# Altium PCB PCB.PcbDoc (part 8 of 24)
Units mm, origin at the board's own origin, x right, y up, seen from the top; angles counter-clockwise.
Board outline 100 x 160 mm, 10 copper layers (TOP_L1, L2, L3, L4, L5, L6, L7, L8, L9, BOTTOM_L10), stack 1.946 mm thick; 1358 components, 1149 nets, 6777 pads, 10914 vias.
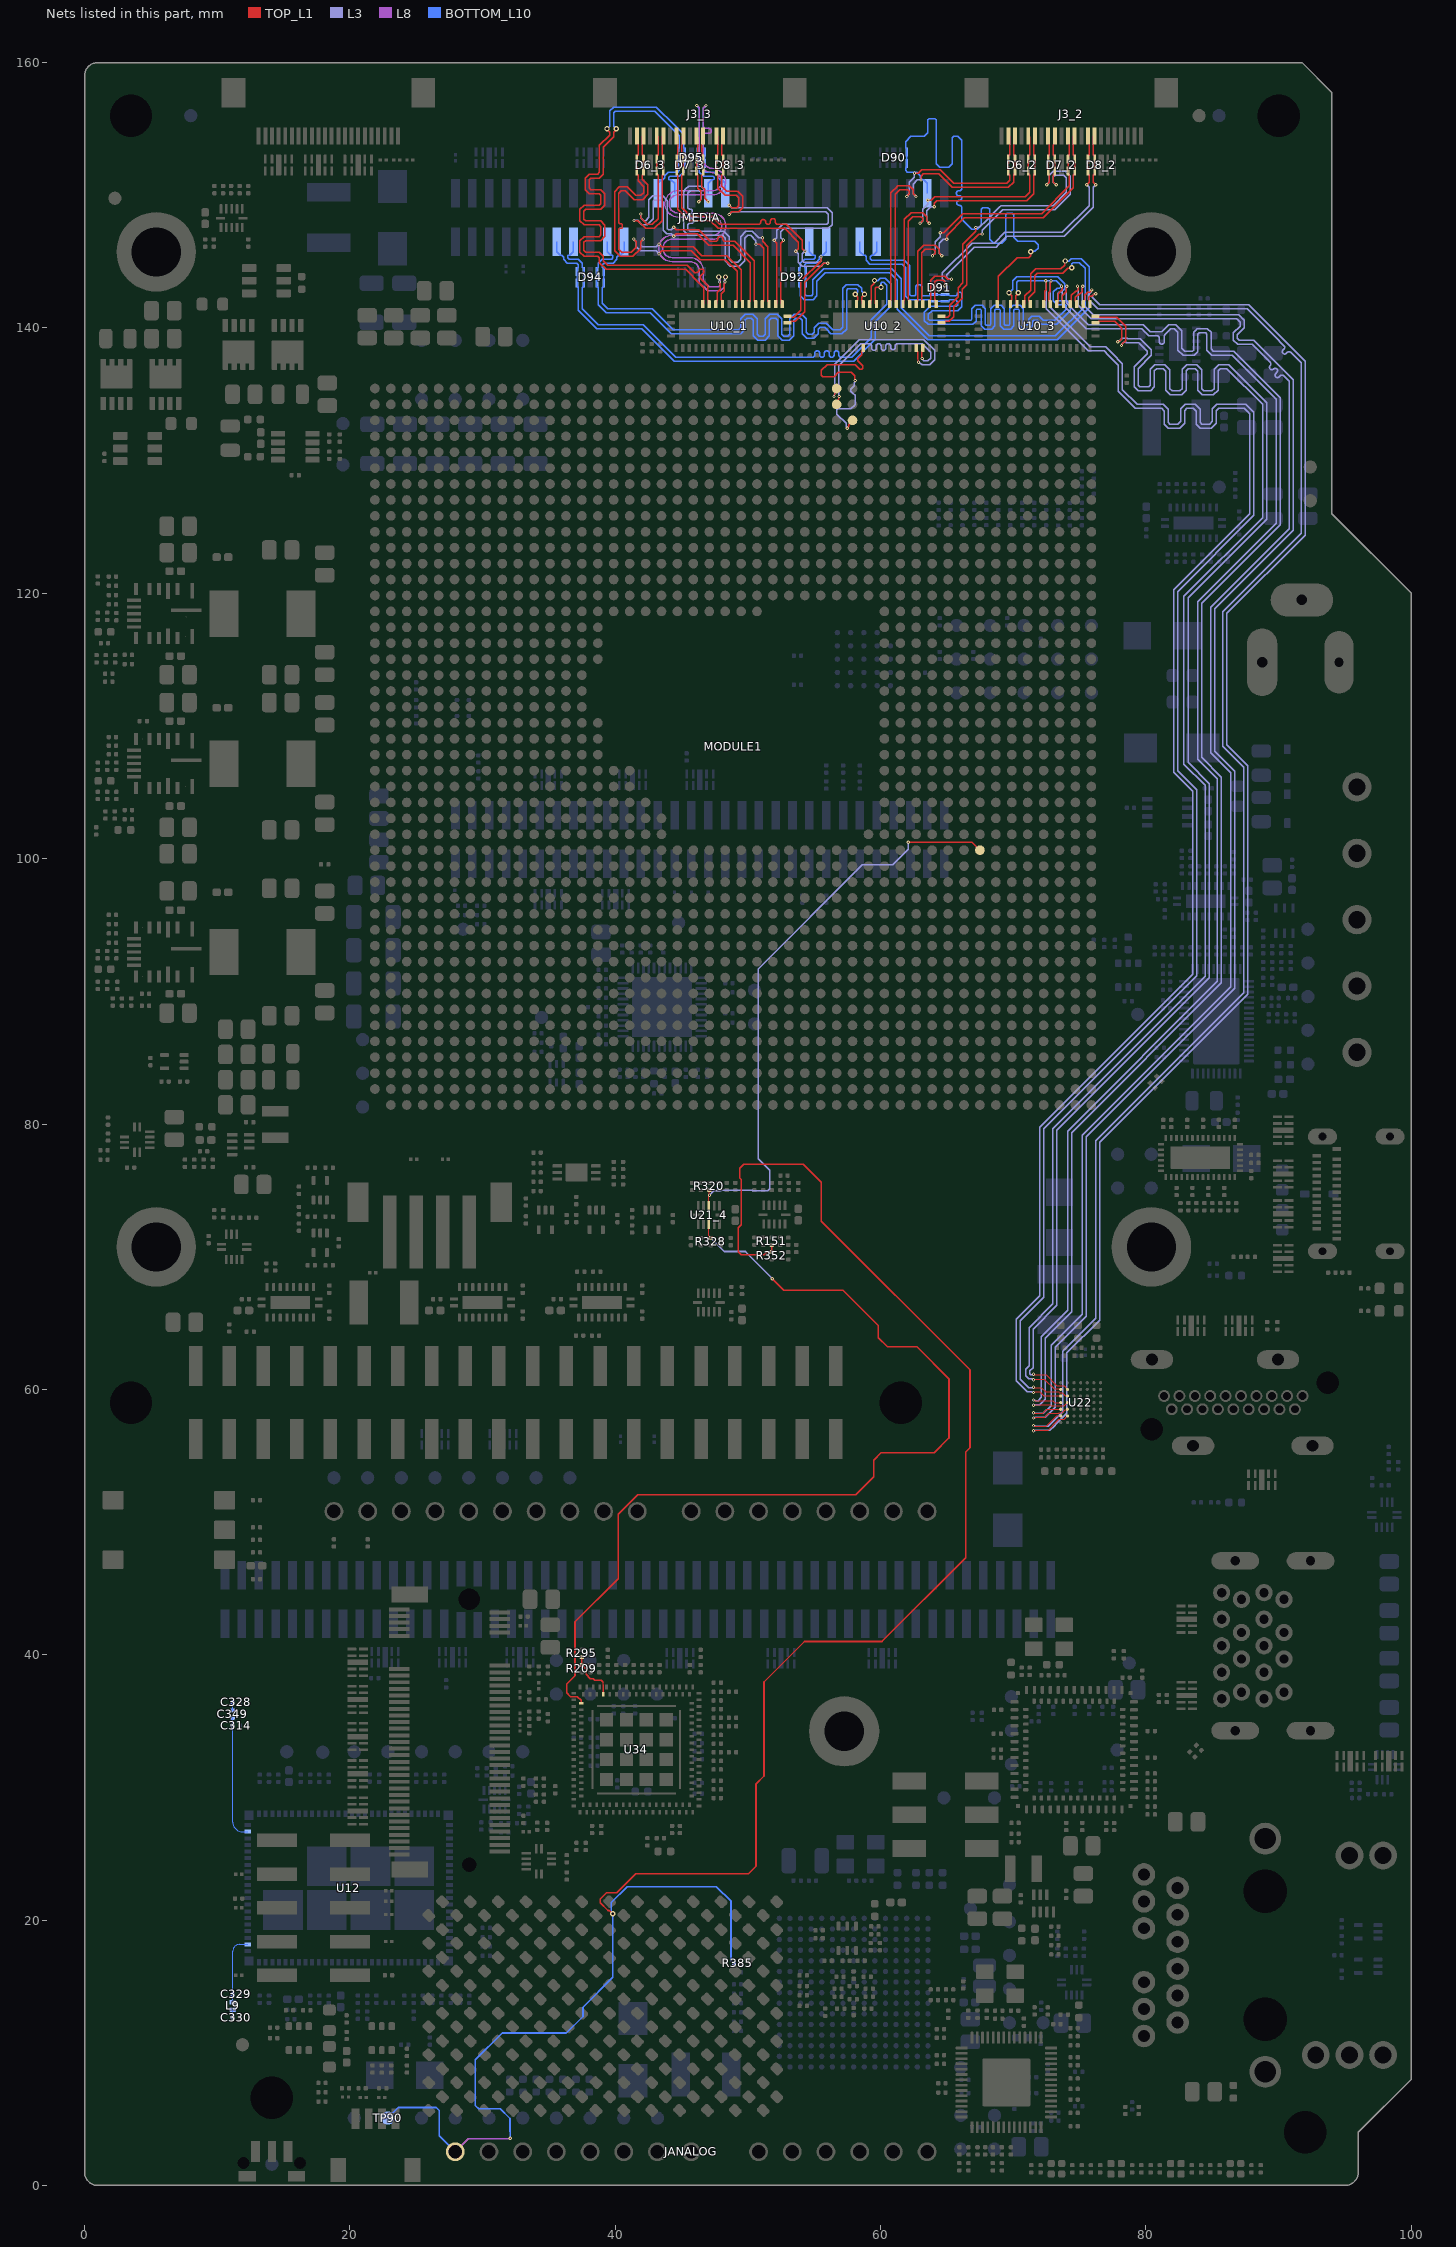
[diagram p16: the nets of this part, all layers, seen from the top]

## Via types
v1: diameter 0.25, hole 0.1, TOP_L1 to L2, tented both sides, 3439 vias
v2: diameter 0.25, hole 0.1, L2 to L3, tented both sides, 2256 vias
v3: diameter 0.25, hole 0.1, L9 to BOTTOM_L10, tented both sides, 1685 vias
v4: diameter 0.25, hole 0.1, L8 to L9, tented both sides, 1675 vias
v5: diameter 0.4, hole 0.2, L3 to L8, tented both sides, 1251 vias
v6: diameter 0.6, hole 0.3, TOP_L1 to BOTTOM_L10, tented both sides, 600 vias
v7: diameter 0.24, hole 0.1, TOP_L1 to L2, tented both sides, 8 vias

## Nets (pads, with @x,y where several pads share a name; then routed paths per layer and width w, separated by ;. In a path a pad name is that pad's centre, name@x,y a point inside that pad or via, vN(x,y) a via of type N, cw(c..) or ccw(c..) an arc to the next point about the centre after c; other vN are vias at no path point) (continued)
A_LN1_3_P: D90.5 D90.6 JMEDIA.4 U10_3.36 | length 43.5
  TOP_L1 w0.109: U10_3.36@68.782,141.791 68.853,141.861 68.853,142.105 68.88,142.132 68.88,143.887 70.297,145.304 71.158,145.304 71.309,145.456 v4(71.309,145.735)
  BOTTOM_L10 w0.109: JMEDIA.4@63.519,150.141 63.519,150.891 63.249,151.161 63.132,151.161 62.985,151.308 62.985,151.468 62.71,151.742 62.017,151.742 61.881,151.878 61.881,152.044 61.979,152.142 D90.6@61.979,152.379 D90.5@61.979,153.254 61.979,153.492 61.882,153.589 61.882,154.04 62.282,154.44 62.348,154.44 63.284,154.44 63.555,154.711 63.555,155.68 63.648,155.773 64.08,155.773 64.173,155.68 64.173,152.391 64.444,152.12 65.128,152.12 65.399,152.391 65.399,154.348 65.492,154.44 65.636,154.44 65.798,154.44 66.104,154.133 66.104,150.934 66.104,150.516 cw(c65.923,150.516) 65.923,150.335 65.886,150.335 ccw(c65.886,150.153) 65.886,149.971 65.923,149.971 cw(c65.923,149.79) 65.923,149.608 65.919,149.608 ccw(c65.919,149.427) 65.919,149.245 65.923,149.245 cw(c65.923,149.063) 66.104,149.063 66.104,148.431 66.104,148.182 66.715,147.571 66.858,147.427 67.285,147.427 67.587,147.729 67.587,148.952 67.711,149.075 68.081,149.075 68.205,148.952 68.205,146.696 68.507,146.394 69.13,146.394 69.432,146.696 69.432,148.529 69.555,148.652 69.925,148.652 70.049,148.529 70.049,146.837 70.351,146.535 71.577,146.535 71.609,146.535 71.876,146.268 71.876,146.012 71.63,145.766 71.44,145.766 71.436,145.762 71.336,145.762 v4(71.309,145.735)
  other v1: 71.309,145.735
  other v2: 71.309,145.735
  other v3: 71.309,145.735
  other v5: 71.309,145.735
A_LN2_1_N: D95.5 D95.6 JMEDIA.36 U10_1.33 | length 40.9
  TOP_L1 w0.109: v3(40.077,155.014) 40.077,154.938 39.879,154.741 39.879,154.407 39.701,154.228 39.109,153.637 39.109,152.975 39.109,151.599 38.8,151.289 38.154,151.289 38.024,151.159 38.024,150.549 38.154,150.418 38.907,150.418 39.216,150.109 39.216,149.246 38.907,148.937 37.769,148.937 37.639,148.807 37.639,148.197 37.769,148.066 38.907,148.066 39.216,147.757 39.216,146.894 38.907,146.585 37.769,146.585 37.639,146.455 37.639,145.845 37.769,145.714 38.8,145.714 39.109,145.405 39.109,145.135 39.109,145.052 39.447,144.713 45.337,144.713 45.437,144.713 45.942,144.209 ccw(c46.071,144.337) 46.199,144.209 46.377,144.386 cw(c46.505,144.258) 46.634,144.386 cw(c46.505,144.258) 46.634,144.13 46.456,143.952 ccw(c46.584,143.823) 46.456,143.695 46.751,143.399 46.985,143.166 46.985,142.132 47.012,142.105 47.012,141.861 U10_1.33@47.082,141.791
  BOTTOM_L10 w0.109: v3(40.077,155.014) 39.879,155.212 39.879,155.909 39.879,156.226 39.994,156.34 42.979,156.34 44.837,154.483 44.837,153.589 44.739,153.492 D95.6@44.739,153.254 44.739,152.142 44.837,152.044 44.837,151.878 44.701,151.742 44.008,151.742 43.733,151.468 43.733,151.308 43.586,151.161 43.47,151.161 43.199,150.891 JMEDIA.36@43.199,150.141
  other v1: 40.077,155.014
  other v2: 40.077,155.014
  other v4: 40.077,155.014
  other v5: 40.077,155.014
A_LN2_1_P: D95.4 D95.7 JMEDIA.34 U10_1.34 | length 41
  TOP_L1 w0.109: v3(39.377,155.014) 39.377,154.938 39.574,154.741 39.574,154.533 38.804,153.763 38.804,152.975 38.804,151.725 38.674,151.594 38.028,151.594 37.719,151.285 37.719,150.423 38.028,150.113 38.781,150.113 38.912,149.983 38.912,149.373 38.781,149.242 37.643,149.242 37.334,148.933 37.334,148.07 37.643,147.761 38.781,147.761 38.912,147.631 38.912,147.021 38.781,146.89 37.643,146.89 37.334,146.581 37.334,145.718 37.643,145.409 38.674,145.409 38.804,145.279 38.804,145.135 38.804,144.925 39.321,144.409 45.311,144.409 46.379,143.341 46.68,143.04 46.68,142.132 46.653,142.105 46.653,141.861 U10_1.34@46.582,141.791
  BOTTOM_L10 w0.109: v3(39.377,155.014) 39.574,155.212 39.574,155.783 39.574,156.352 39.867,156.645 43.106,156.645 44.49,155.261 44.595,155.156 45.142,154.609 45.142,153.589 45.239,153.492 D95.7@45.239,153.254 45.239,152.142 45.141,152.044 45.141,151.752 44.827,151.437 44.134,151.437 44.038,151.341 44.038,151.206 44.082,151.161 44.199,151.161 44.469,150.891 JMEDIA.34@44.469,150.141
  other v1: 39.377,155.014
  other v2: 39.377,155.014
  other v4: 39.377,155.014
  other v5: 39.377,155.014
A_LN2_2_N: D94.1 D94.10 JMEDIA.39 U10_2.33 | length 39.1
  TOP_L1 w0.109: U10_2.33@58.682,141.791 58.612,141.861 58.612,142.105 58.585,142.132 58.585,142.299 58.782,142.496 v3(58.782,142.54)
  BOTTOM_L10 w0.109: D94.1@39.119,143.379 D94.10@39.119,144.254 39.119,144.491 39.021,144.589 39.021,144.755 39.157,144.891 39.85,144.891 40.125,145.165 40.125,145.324 40.272,145.472 40.389,145.472 40.659,145.742 JMEDIA.39@40.659,146.492 ; D94.1@39.119,143.379 39.119,143.142 39.021,143.044 39.021,141.858 39.439,141.441 42.77,141.441 44.355,139.856 49.17,139.856 49.314,139.856 49.469,140.01 49.469,140.688 49.802,141.021 50.363,141.021 50.695,140.688 50.695,139.532 50.85,139.377 51.158,139.377 51.313,139.532 51.313,140.688 51.646,141.021 52.207,141.021 52.54,140.688 52.54,139.532 52.694,139.377 53.002,139.377 53.157,139.532 53.157,140.688 53.49,141.021 54.051,141.021 54.384,140.688 54.384,139.692 54.538,139.537 54.846,139.537 55.001,139.692 55.001,140.01 55.334,140.343 55.895,140.343 56.228,140.01 56.382,139.856 56.599,139.856 56.948,139.856 57.131,140.038 57.131,142.976 57.405,143.25 58.286,143.25 58.561,142.976 58.561,142.762 v3(58.782,142.54)
  other v1: 58.782,142.54
  other v2: 58.782,142.54
  other v4: 58.782,142.54
  other v5: 58.782,142.54
A_LN2_2_P: D94.2 D94.9 JMEDIA.41 U10_2.34 | length 39
  TOP_L1 w0.109: v2(58.082,142.54) 58.082,142.496 58.28,142.299 58.28,142.132 58.253,142.105 58.253,141.861 U10_2.34@58.182,141.791
  BOTTOM_L10 w0.109: D94.2@38.619,143.379 38.619,144.491 38.717,144.589 38.717,144.881 39.031,145.196 39.724,145.196 39.82,145.292 39.82,145.427 39.776,145.472 39.659,145.472 39.389,145.742 JMEDIA.41@39.389,146.492 ; D94.2@38.619,143.379 38.619,143.142 38.717,143.044 38.717,141.732 38.924,141.525 39.313,141.136 42.644,141.136 44.039,139.741 44.229,139.551 49.17,139.551 49.441,139.551 49.773,139.884 49.773,140.562 49.928,140.716 50.236,140.716 50.391,140.562 50.391,139.405 50.724,139.072 51.285,139.072 51.617,139.405 51.617,140.562 51.772,140.716 52.08,140.716 52.235,140.562 52.235,139.405 52.568,139.072 53.129,139.072 53.462,139.405 53.462,140.562 53.616,140.716 53.924,140.716 54.079,140.562 54.079,139.565 54.412,139.233 54.973,139.233 55.306,139.565 55.306,139.884 55.46,140.038 55.768,140.038 55.923,139.884 56.256,139.551 56.599,139.551 57.074,139.551 57.436,139.912 57.436,142.85 57.532,142.946 58.16,142.946 58.256,142.85 58.256,142.714 v2(58.082,142.54)
  other v1: 58.082,142.54
  other v3: 58.082,142.54
  other v4: 58.082,142.54
  other v5: 58.082,142.54
A_LN2_3_N: D91.4 D91.7 JMEDIA.9 U10_3.33 | length 43.7
  TOP_L1 w0.109: U10_3.33@70.282,141.791 70.212,141.861 70.212,142.105 70.171,142.146 70.171,142.42 70.369,142.618 v3(70.369,142.661)
  BOTTOM_L10 w0.109: JMEDIA.9@59.709,146.492 59.709,145.742 59.439,145.472 59.322,145.472 59.227,145.376 59.227,145.211 59.322,145.115 61.761,145.115 62.204,144.671 62.204,142.514 62.3,142.418 62.564,142.418 62.66,142.514 62.66,143.152 62.756,143.248 62.97,143.248 63.083,143.134 63.083,142.514 63.179,142.418 63.655,142.418 63.753,142.515 D91.4@64.866,142.515 ; D91.4@64.866,142.515 64.911,142.47 65.148,142.47 65.201,142.418 65.667,142.418 65.763,142.514 65.763,142.539 65.775,142.551 65.775,142.604 65.878,142.707 66.014,142.707 66.11,142.611 66.11,141.592 65.83,141.313 63.877,141.313 63.604,141.04 63.604,140.669 63.7,140.573 66.674,140.573 66.818,140.573 66.882,140.637 66.882,141.464 67.122,141.704 67.661,141.704 67.901,141.464 67.901,140.275 67.962,140.213 68.249,140.213 68.31,140.275 68.31,141.464 68.55,141.704 69.089,141.704 69.329,141.464 69.329,140.275 69.39,140.213 69.677,140.213 69.738,140.275 69.738,141.464 69.978,141.704 70.517,141.704 70.757,141.464 70.757,140.317 70.818,140.255 71.105,140.255 71.166,140.317 71.166,140.637 71.406,140.877 71.945,140.877 72.185,140.637 72.249,140.573 72.603,140.573 73.137,140.573 73.989,141.425 73.989,141.523 73.989,141.667 73.896,141.76 73.297,141.76 73.026,142.031 73.026,142.716 73.297,142.987 73.464,142.987 73.557,143.079 73.557,143.21 73.227,143.54 71.394,143.54 70.959,143.54 70.37,143.54 70.274,143.445 70.274,142.794 70.369,142.699 v3(70.369,142.661)
  other v1: 70.369,142.661
  other v2: 70.369,142.661
  other v4: 70.369,142.661
  other v5: 70.369,142.661
A_LN2_3_P: D91.5 D91.6 JMEDIA.11 U10_3.34 | length 43.6
  TOP_L1 w0.109: v3(69.669,142.661) 69.669,142.618 69.866,142.42 69.866,142.119 69.853,142.105 69.853,141.861 U10_3.34@69.782,141.791
  BOTTOM_L10 w0.109: JMEDIA.11@58.439,146.492 58.439,145.742 58.71,145.472 58.826,145.472 58.922,145.376 58.922,145.084 59.196,144.81 61.634,144.81 61.899,144.545 61.899,142.387 62.174,142.113 63.655,142.113 63.753,142.015 D91.6@63.865,142.015 ; D91.6@63.991,142.015 D91.5@64.866,142.015 65.103,142.015 65.201,142.113 65.646,142.113 65.805,141.954 65.805,141.718 65.704,141.618 63.751,141.618 63.299,141.166 63.299,140.543 63.574,140.268 66.674,140.268 66.944,140.268 67.187,140.511 67.187,141.338 67.248,141.399 67.535,141.399 67.596,141.338 67.596,140.148 67.836,139.909 68.375,139.909 68.615,140.148 68.615,141.338 68.676,141.399 68.963,141.399 69.024,141.338 69.024,140.148 69.264,139.909 69.803,139.909 70.043,140.148 70.043,141.338 70.104,141.399 70.391,141.399 70.452,141.338 70.452,140.19 70.692,139.95 71.231,139.95 71.471,140.19 71.471,140.511 71.532,140.572 71.819,140.572 71.88,140.511 72.123,140.268 72.603,140.268 73.263,140.268 74.294,141.299 74.294,141.523 74.294,141.793 74.023,142.065 73.423,142.065 73.331,142.157 73.331,142.589 73.423,142.682 73.591,142.682 73.862,142.953 73.862,143.336 73.558,143.64 73.353,143.845 71.085,143.845 ; v3(69.669,142.661) 69.7,142.661 69.969,142.931 69.969,143.571 70.244,143.845 71.085,143.845
  other v1: 69.669,142.661
  other v2: 69.669,142.661
  other v4: 69.669,142.661
  other v5: 69.669,142.661
A_LN3_1_N: D95.2 D95.9 JMEDIA.30 U10_1.31 | length 41
  TOP_L1 w0.109: U10_1.31@48.082,141.791 48.012,141.861 48.012,142.105 47.985,142.132 47.985,142.566 48.214,142.796 48.214,143.323 48.243,143.351 48.243,143.451 v2(48.27,143.478)
  L3 w0.104: v2(48.27,143.478) 48.287,143.495 48.287,143.823 v5(48.304,143.84)
  L8 w0.104: v3(46.139,156.765) 46.327,156.577 46.327,153.796 46.327,152.706 ccw(c47.319,152.706) 47.319,151.714 cw(c47.319,151.027) 47.319,150.34 44.735,150.34 ccw(c44.735,149.348) 44.735,148.356 47.328,148.356 cw(c47.328,147.669) 47.328,146.982 44.275,146.982 ccw(c44.275,145.99) 44.275,144.998 45.64,144.998 cw(c45.64,144.311) 46.327,144.311 46.327,144.107 46.327,143.416 46.951,142.793 47.915,142.793 48.207,143.084 48.207,143.601 48.248,143.642 48.248,143.784 v5(48.304,143.84)
  BOTTOM_L10 w0.109: v3(46.139,156.765) 46.337,156.567 46.337,153.589 46.239,153.492 D95.9@46.239,153.254 46.239,152.142 46.337,152.044 46.337,151.752 46.651,151.437 47.344,151.437 47.44,151.341 47.44,151.206 47.396,151.161 47.279,151.161 47.009,150.891 JMEDIA.30@47.009,150.141
  other v1: 48.27,143.478
  other v4: 46.139,156.765
A_LN3_1_P: D95.1 D95.10 JMEDIA.28 U10_1.32 | length 40.9
  TOP_L1 w0.109: U10_1.32@47.582,141.791 47.653,141.861 47.653,142.105 47.68,142.132 47.68,142.693 47.91,142.923 47.91,143.307 47.881,143.336 47.881,143.435 v2(47.854,143.462)
  L3 w0.104: v5(47.804,143.84) 47.829,143.815 47.829,143.487 v2(47.854,143.462)
  L8 w0.104: v3(46.839,156.765) 46.836,156.765 46.632,156.56 46.632,156.051 46.632,155.213 ccw(c46.811,155.213) 46.811,155.034 47.057,155.034 cw(c47.057,154.855) 47.057,154.676 46.811,154.676 ccw(c46.811,154.497) 46.632,154.497 46.632,154.087 46.632,153.796 46.632,152.706 ccw(c47.319,152.706) 47.319,152.019 cw(c47.319,151.027) 47.319,150.035 44.735,150.035 ccw(c44.735,149.348) 44.735,148.661 47.328,148.661 cw(c47.328,147.669) 47.328,146.677 44.275,146.677 ccw(c44.275,145.99) 44.275,145.303 45.64,145.303 cw(c45.64,144.311) 46.632,144.311 46.632,144.107 46.632,143.542 47.077,143.097 47.789,143.097 47.902,143.21 47.902,143.601 47.861,143.642 47.861,143.784 v5(47.804,143.84)
  BOTTOM_L10 w0.109: v3(46.839,156.765) 46.642,156.567 46.642,153.589 46.739,153.492 D95.10@46.739,153.254 D95.1@46.739,152.379 46.739,152.142 46.641,152.044 46.641,151.878 46.777,151.742 47.47,151.742 47.745,151.468 47.745,151.308 47.892,151.161 48.009,151.161 48.279,150.891 JMEDIA.28@48.279,150.141
  other v1: 47.854,143.462
  other v4: 46.839,156.765
A_LN3_2_N: D94.4 D94.7 JMEDIA.45 U10_2.31 | length 39.1
  TOP_L1 w0.109: U10_2.31@59.682,141.791 59.612,141.861 59.612,142.105 59.585,142.132 59.585,142.981 59.68,143.077 v3(60.028,143.077)
  BOTTOM_L10 w0.109: JMEDIA.45@36.849,146.492 36.849,145.742 36.579,145.472 36.462,145.472 36.418,145.427 36.418,145.292 36.514,145.196 37.207,145.196 37.521,144.881 37.521,144.589 37.619,144.491 D94.4@37.619,143.379 ; D94.4@37.619,143.379 37.619,143.142 37.521,143.044 37.521,141.441 38.721,140.241 42.124,140.241 43.703,138.662 44.575,137.789 53.558,137.789 54.854,137.789 ccw(c54.854,137.971) 55.036,137.971 55.036,138.091 cw(c55.217,138.091) 55.399,138.091 55.399,137.971 ccw(c55.58,137.971) 55.762,137.971 55.762,138.091 cw(c55.944,138.091) 56.125,138.091 56.125,137.971 ccw(c56.307,137.971) 56.488,137.971 56.488,138.091 cw(c56.67,138.091) 56.852,138.091 56.852,137.971 ccw(c57.033,137.971) 57.033,137.789 57.451,137.789 57.83,137.789 59.304,139.264 59.304,140.611 59.483,140.789 60.462,141.768 60.462,143.206 60.238,143.43 60.102,143.43 60.006,143.334 60.006,143.099 v3(60.028,143.077)
  other v1: 60.028,143.077
  other v2: 60.028,143.077
  other v4: 60.028,143.077
  other v5: 60.028,143.077
A_LN3_2_P: D94.5 D94.6 JMEDIA.47 U10_2.32 | length 39.2
  TOP_L1 w0.109: U10_2.32@59.182,141.791 59.253,141.861 59.253,142.105 59.28,142.132 59.28,143.133 59.508,143.362 59.508,143.546 v2(59.533,143.572)
  BOTTOM_L10 w0.109: JMEDIA.47@35.579,146.492 35.579,145.742 35.85,145.472 35.966,145.472 36.113,145.324 36.113,145.165 36.388,144.891 37.081,144.891 37.217,144.755 37.217,144.589 37.119,144.491 D94.5@37.119,143.379 ; D94.5@37.119,143.379 37.119,143.142 37.217,143.044 37.217,141.314 38.595,139.936 41.998,139.936 43.592,138.342 44.449,137.485 57.956,137.485 59.609,139.138 59.609,140.485 60.766,141.642 60.766,143.332 60.364,143.735 59.976,143.735 59.791,143.55 59.555,143.55 v2(59.533,143.572)
  other v1: 59.533,143.572
  other v3: 59.533,143.572
  other v4: 59.533,143.572
  other v5: 59.533,143.572
A_LN3_3_N: D92.1 D92.10 JMEDIA.15 U10_3.31 | length 41.9
  TOP_L1 w0.109: U10_3.31@71.282,141.791 71.282,141.966 71.171,142.077 71.171,142.286 71.609,142.724 71.609,143.945 71.804,144.14 73.715,144.14 74.089,144.514 74.368,144.514 v1(74.399,144.545)
  BOTTOM_L10 w0.109: JMEDIA.15@55.899,146.492 55.899,145.742 55.629,145.472 55.512,145.472 55.365,145.324 55.365,145.165 55.09,144.891 54.397,144.891 54.261,144.755 54.261,144.589 54.359,144.491 D92.10@54.359,144.254 D92.1@54.359,143.379 54.359,143.141 54.262,143.044 54.262,142.563 54.382,142.443 54.8,142.443 54.896,142.539 54.896,143.628 55.074,143.806 55.717,144.449 60.826,144.449 61.551,143.724 61.551,141.539 63.674,139.416 73.169,139.416 75.404,141.65 75.404,144.497 74.977,144.924 74.499,144.924 74.399,144.825 v1(74.399,144.545)
  other v2: 74.399,144.545
  other v3: 74.399,144.545
  other v4: 74.399,144.545
  other v5: 74.399,144.545
A_LN3_3_P: D92.2 D92.9 JMEDIA.17 U10_3.32 | length 43.8
  TOP_L1 w0.109: U10_3.32@70.782,141.791 70.853,141.861 70.853,142.119 70.866,142.132 70.866,142.413 71.304,142.851 71.304,144.071 71.678,144.445 73.588,144.445 73.873,144.73 73.873,145.009 v1(73.904,145.04)
  BOTTOM_L10 w0.109: D92.2@53.859,143.379 53.859,144.491 53.957,144.589 53.957,144.881 54.271,145.196 54.964,145.196 55.06,145.292 55.06,145.427 55.016,145.472 54.899,145.472 54.629,145.742 JMEDIA.17@54.629,146.492 ; D92.2@53.859,143.379 53.859,143.141 53.957,143.044 53.957,142.437 54.255,142.138 54.926,142.138 55.201,142.413 55.201,143.502 55.843,144.144 60.7,144.144 61.247,143.598 61.247,141.413 63.548,139.111 73.296,139.111 75.708,141.524 75.708,144.624 75.103,145.229 74.373,145.229 74.184,145.04 v1(73.904,145.04)
  other v2: 73.904,145.04
  other v3: 73.904,145.04
  other v4: 73.904,145.04
  other v5: 73.904,145.04
ANT0_29: C329.2 L9.1 U12.78 | length 5.5
  BOTTOM_L10 w0.09: L9.1@11.167,13.801 C329.2@11.167,14.401 ; 11.167,14.151 11.167,17.654 cw(c11.674,17.654) 11.674,18.161 U12.78@12.3,18.16
ANT0_PI_29: C330.2 L9.2 | length 0.6
  BOTTOM_L10 w0.09: C330.2@11.167,12.651 L9.2@11.167,13.251
ANT1_29: C314.2 C349.2 U12.95 | length 9.4
  BOTTOM_L10 w0.09: C349.2@11.167,35.251 C314.2@11.167,34.651 11.167,27.374 ccw(c11.881,27.374) 11.881,26.66 U12.95@12.3,26.66
ANT1_PI_29: C328.2 C349.1 | length 0.6
  BOTTOM_L10 w0.09: C349.1@11.167,35.801 C328.2@11.167,36.401
B_CLK_1_N: D7_3.1 D7_3.10 J3_3.8 U10_1.20 | length 26
  TOP_L1 w0.109: J3_3.8@44.624,154.475 44.72,154.38 44.72,153.818 44.722,153.816 44.722,153.052 44.624,152.954 D7_3.10@44.624,152.717 D7_3.1@44.624,151.842 44.624,151.604 44.722,151.506 44.722,148.947 45.172,148.497 45.574,148.095 47.165,148.095 47.751,147.509 52.76,147.509 53.795,146.474 53.795,145.986 v2(53.598,145.788) ; U10_1.20@52.982,140.391 53.157,140.391 53.255,140.488 53.572,140.488 54.295,141.211 54.295,143.434 55.724,144.864 v1(56.004,144.865)
  L3 w0.104: v2@53.598,145.78 53.606,145.78 53.8,145.586 53.8,145.138 53.8,144.938 54.089,144.649 55.509,144.649 55.725,144.865 v1(56.004,144.865)
  other v1: 53.598,145.788
  other v2: 56.004,144.865
B_CLK_1_P: D7_3.2 D7_3.9 J3_3.9 U10_1.21 | length 26
  TOP_L1 w0.109: J3_3.9@45.124,154.475 45.029,154.38 45.029,153.818 45.027,153.816 45.027,153.052 45.124,152.954 D7_3.9@45.124,152.717 D7_3.2@45.124,151.842 45.124,151.604 45.027,151.506 45.027,149.073 45.3,148.8 45.7,148.4 47.291,148.4 47.47,148.221 47.878,147.813 49.902,147.813 50.788,147.813 ccw(c50.788,147.995) 50.97,147.995 cw(c51.151,147.995) 51.333,147.995 ccw(c51.515,147.995) 51.696,147.995 51.696,148.06 cw(c51.878,148.06) 52.059,148.06 52.059,147.995 ccw(c52.241,147.995) 52.241,147.813 52.659,147.813 52.887,147.813 54.1,146.6 54.1,145.986 v2(54.298,145.788) ; U10_1.21@52.982,140.891 53.157,140.891 53.255,140.793 53.446,140.793 53.99,141.337 53.99,143.561 55.509,145.08 v1(55.509,145.36)
  L3 w0.104: v2(54.298,145.788) 54.104,145.594 54.104,145.065 54.215,144.954 55.383,144.954 55.509,145.08 v1(55.509,145.36)
  other v1: 54.298,145.788
  other v2: 55.509,145.36
B_CLK_2_N: D7_2.1 D7_2.10 J3_2.8 U10_2.20 | length 24.3
  TOP_L1 w0.109: U10_2.20@64.582,140.391 64.757,140.391 64.855,140.489 65.172,140.489 65.513,140.829 65.513,141.593 66.142,142.223 66.142,142.909 66.5,143.266 66.5,146.194 67.384,147.078 v2(67.664,147.078) ; v1(72.524,150.8) 72.722,150.998 72.722,151.506 72.624,151.604 D7_2.1@72.624,151.842 D7_2.10@72.624,152.717 72.624,152.954 72.722,153.052 72.722,153.816 72.72,153.818 72.72,154.38 J3_2.8@72.624,154.475
  L3 w0.104: v2(67.664,147.078) 67.664,147.358 69.206,148.9 73.12,148.9 73.66,149.44 74.305,150.085 74.305,151.433 73.926,151.811 73.023,151.811 72.722,151.511 72.722,150.998 v1(72.524,150.8)
  other v1: 67.664,147.078
  other v2: 72.524,150.8
B_CLK_2_P: D7_2.2 D7_2.9 J3_2.9 U10_2.21 | length 22.8
  TOP_L1 w0.109: U10_2.21@64.582,140.891 64.757,140.891 64.855,140.793 65.046,140.793 65.208,140.955 65.208,141.719 65.838,142.349 65.838,143.035 66.195,143.393 66.195,146.32 67.169,147.293 v1@67.169,147.573 ; J3_2.9@73.124,154.475 73.029,154.38 73.029,153.818 73.027,153.816 73.027,153.052 73.124,152.954 D7_2.9@73.124,152.717 D7_2.2@73.124,151.842 73.124,151.604 73.027,151.506 73.027,150.998 v1(73.224,150.8)
  L3 w0.104: v1(67.169,147.573) 67.449,147.573 67.997,148.121 68.991,149.116 69.08,149.205 69.702,149.205 72.799,149.205 72.993,149.205 74,150.211 74,151.306 73.8,151.506 73.149,151.506 73.027,151.384 73.027,150.998 v1(73.224,150.8)
  other v2: 67.169,147.573 73.224,150.8
B_CLK_3_N: U10_3.20 U22.F2 | length 113.8
  TOP_L1 w0.064: 73.277,60.282 73.305,60.254 73.821,60.254 U22.F2@74.075,60
  TOP_L1 w0.086: v2(71.517,61.132) 71.548,61.1 71.633,61.1 71.65,61.084 72.475,61.084 73.277,60.282
  TOP_L1 w0.109: U10_3.20@76.182,140.391 76.357,140.391 76.455,140.489 77.65,140.489 78.156,139.983 78.156,139.17 78.005,139.019 77.976,139.019 77.914,138.958 v1(77.876,138.958)
  L3 w0.104: v2(71.517,61.132) 71.493,61.108 71.304,61.108 71.243,61.169 71.243,61.402 71.487,61.646 71.487,64.532 73.289,66.334 73.289,79.532 84.763,91.007 84.763,105.655 83.167,107.252 83.167,119.661 89.09,125.584 89.09,134.379 86.228,137.241 85.476,137.241 85.132,136.897 85.132,135.431 84.96,135.259 84.36,135.259 84.202,135.417 84.202,136.867 83.828,137.241 83.076,137.241 82.732,136.897 82.732,135.431 82.56,135.259 81.96,135.259 81.802,135.417 81.802,136.867 81.428,137.241 80.676,137.241 80.332,136.897 80.332,135.675 80.213,135.557 79.544,135.557 79.402,135.698 79.402,136.936 80.412,137.946 80.412,138.357 79.757,139.012 ; v1(77.876,138.958) 77.916,138.958 77.977,139.019 78.005,139.019 78.198,139.212 78.598,139.212 78.619,139.191 79.578,139.191 79.757,139.012
  other v1: 71.517,61.132
  other v2: 77.876,138.958
B_CLK_3_P: U10_3.21 U22.G2 | length 113.7
  TOP_L1 w0.086: v1(71.517,60.732) 71.548,60.763 71.633,60.763 71.65,60.779 72.349,60.779 73.075,60.053 73.522,60.053 U22.G2@73.575,60
  TOP_L1 w0.109: U10_3.21@76.182,140.891 76.357,140.891 76.455,140.793 77.777,140.793 78.461,140.109 78.461,139.044 78.22,138.804 78.22,138.775 78.159,138.713 v1(78.159,138.675)
  L3 w0.104: v1(71.517,60.732) 71.478,60.732 71.406,60.803 71.178,60.803 70.938,61.042 70.938,61.528 71.182,61.772 71.182,64.658 72.984,66.46 72.984,79.659 84.459,91.133 84.459,105.529 82.862,107.125 82.862,119.787 88.785,125.711 88.785,134.253 86.102,136.936 85.602,136.936 85.437,136.771 85.437,135.305 85.086,134.954 84.234,134.954 83.897,135.291 83.897,136.741 83.702,136.936 83.202,136.936 83.037,136.771 83.037,135.305 82.686,134.954 81.834,134.954 81.497,135.291 81.497,136.741 81.302,136.936 80.802,136.936 80.637,136.771 80.637,135.549 80.34,135.252 79.417,135.252 79.097,135.572 79.097,137.062 80.107,138.072 80.107,138.231 79.452,138.886 78.493,138.886 78.472,138.908 78.324,138.908 78.22,138.803 78.22,138.776 78.159,138.715 v1(78.159,138.675)
  other v2: 71.517,60.732 78.159,138.675
B_LN0_1_N: D6_3.1 D6_3.10 J3_3.2 U10_1.28 | length 26
  TOP_L1 w0.109: J3_3.2@41.72,153.944 41.72,153.786 41.722,153.784 41.722,153.052 41.624,152.954 41.624,151.604 41.712,151.517 41.712,151.084 42.139,150.657 42.139,150.184 41.937,149.982 41.542,149.982 40.888,150.636 40.306,150.636 39.946,150.276 39.946,145.819 40.37,145.395 41.326,145.395 41.902,145.971 41.902,146.502 v1(42.1,146.7) ; v1@43.301,146.302 43.498,146.105 45.866,146.105 46.514,145.456 48.416,145.456 49.485,144.388 49.485,142.063 49.582,141.966 U10_1.28@49.582,141.791
  L3 w0.104: v1(42.1,146.7) 41.902,146.502 41.902,146.237 42.034,146.105 43.102,146.105 v1(43.3,146.302)
  other v2: 43.3,146.302 42.1,146.7
B_LN0_1_P: D6_3.2 D6_3.9 J3_3.3 U10_1.29 | length 26
  TOP_L1 w0.109: v2(41.4,146.7) 41.598,146.502 41.598,146.098 41.2,145.7 40.496,145.7 40.251,145.945 40.251,146.973 40.251,147.391 cw(c40.36,147.391) 40.36,147.5 40.426,147.5 ccw(c40.426,147.609) 40.535,147.609 40.535,147.754 ccw(c40.426,147.754) 40.426,147.863 40.36,147.863 cw(c40.36,147.973) 40.251,147.973 40.251,149.485 40.251,150.15 40.432,150.331 40.762,150.331 41.237,149.856 41.416,149.678 42.063,149.678 42.444,150.058 42.444,150.783 42.016,151.21 42.016,151.496 42.124,151.604 D6_3.9@42.124,152.717 42.124,152.954 42.027,153.052 42.027,153.816 42.029,153.818 42.029,154.38 J3_3.3@42.124,154.475 ; v1@43.301,145.602 43.498,145.8 45.74,145.8 46.388,145.152 48.29,145.152 49.18,144.262 49.18,142.063 49.082,141.966 U10_1.29@49.082,141.791
  L3 w0.104: v2(41.4,146.7) 41.598,146.502 41.598,146.111 41.908,145.8 43.102,145.8 v2(43.3,145.602)
  other v1: 43.3,145.602 41.4,146.7
B_LN0_2_N: D6_2.1 D6_2.10 J3_2.2 U10_2.28 | length 23.3
  TOP_L1 w0.109: U10_2.28@61.182,141.791 61.182,141.966 61.085,142.064 61.085,150.074 61.426,150.415 62.038,150.415 62.166,150.288 62.166,150.107 v1(61.968,149.908) ; v2(62.551,151.648) 62.828,151.648 63.095,151.915 64.5,151.915 64.679,151.736 65.515,150.9 69.5,150.9 69.722,151.122 69.722,151.506 69.624,151.604 D6_2.1@69.624,151.842 D6_2.10@69.624,152.717 69.624,152.954 69.722,153.052 69.722,153.661 69.722,153.768 69.72,153.77 69.72,154.38 J3_2.2@69.624,154.475
  L3 w0.104: v1(61.968,149.908) 62.166,150.106 62.166,150.325 62.16,150.331 62.16,150.968 62.551,151.359 v2(62.551,151.648)
  other v1: 62.551,151.648
  other v2: 61.968,149.908
B_LN0_2_P: D6_2.2 D6_2.9 J3_2.3 U10_2.29 | length 24.3
  TOP_L1 w0.109: U10_2.29@60.682,141.791 60.682,141.966 60.78,142.064 60.78,150.2 60.958,150.379 61.121,150.542 61.3,150.72 62.164,150.72 62.47,150.414 62.47,150.107 v2(62.668,149.908) ; v2(63.046,151.153) 63.046,151.435 63.221,151.61 64.374,151.61 65.389,150.595 69.626,150.595 70.027,150.996 70.027,151.506 70.124,151.604 D6_2.2@70.124,151.842 D6_2.9@70.124,152.717 70.124,152.954 70.027,153.052 70.027,153.673 70.027,153.816 70.029,153.818 70.029,154.38 J3_2.3@70.124,154.475
  L3 w0.104: v2(62.668,149.908) 62.47,150.106 62.47,150.451 62.465,150.457 62.465,150.841 62.777,151.153 v2(63.046,151.153)
  other v1: 62.668,149.908 63.046,151.153
B_LN0_3_N: U10_3.28 U22.F3 | length 113.8
  TOP_L1 w0.064: 73.075,59.805 73.423,59.805 73.473,59.754 73.68,59.754 73.905,59.53
  TOP_L1 w0.084: 73.905,59.53 74.045,59.53 U22.F3@74.075,59.5
  TOP_L1 w0.086: v1(71.517,60.166) 71.548,60.135 71.633,60.135 71.65,60.118 72.113,60.118 72.427,59.805 73.075,59.805
  TOP_L1 w0.109: U10_3.28@72.782,141.791 72.782,141.966 72.685,142.064 72.685,142.644 72.789,142.748 72.789,143.415 72.81,143.435 72.81,143.522 v2(72.836,143.549)
  L3 w0.104: v1(71.517,60.166) 71.489,60.138 71.403,60.138 71.383,60.118 71.173,60.118 70.526,60.766 70.526,65.171 72.289,66.934 72.289,79.632 83.813,91.157 83.813,105.205 82.389,106.629 82.389,120.125 88.129,125.865 88.129,133.64 87.533,134.236 85.35,134.236 85.006,133.892 85.006,132.952 84.805,132.751 84.205,132.751 84.076,132.88 84.076,133.862 83.702,134.236 82.95,134.236 82.606,133.892 82.606,132.952 82.405,132.751 81.805,132.751 81.676,132.88 81.676,133.862 81.302,134.236 79.333,134.236 78.22,135.349 78.22,137.319 77.461,138.078 76.969,138.57 75.792,138.57 72.789,141.573 72.789,143.415 72.809,143.435 72.809,143.521 v2(72.836,143.549)
  other v1: 72.836,143.549
  other v2: 71.517,60.166
B_LN0_3_P: U10_3.29 U22.G3 | length 113.7
  TOP_L1 w0.084: 73.075,59.5 U22.G3@73.575,59.5
  TOP_L1 w0.086: v2(71.517,59.766) 71.548,59.797 71.633,59.797 71.65,59.813 71.987,59.813 72.3,59.5 73.075,59.5
  TOP_L1 w0.109: U10_3.29@72.282,141.791 72.282,141.966 72.38,142.064 72.38,142.77 72.484,142.875 72.484,143.415 72.463,143.435 72.463,143.522 v2(72.436,143.549)
  L3 w0.104: v2(71.517,59.766) 71.489,59.794 71.403,59.794 71.383,59.813 71.047,59.813 70.221,60.639 70.221,65.297 71.984,67.06 71.984,79.759 83.509,91.283 83.509,105.078 82.084,106.503 82.084,120.252 87.824,125.992 87.824,133.514 87.407,133.931 85.476,133.931 85.311,133.766 85.311,132.826 84.931,132.446 84.078,132.446 83.771,132.754 83.771,133.736 83.576,133.931 83.076,133.931 82.911,133.766 82.911,132.826 82.531,132.446 81.678,132.446 81.371,132.754 81.371,133.736 81.176,133.931 79.207,133.931 77.915,135.223 77.915,137.193 77.154,137.953 76.843,138.265 75.666,138.265 72.484,141.447 72.484,141.746 72.484,143.415 72.464,143.435 72.464,143.521 v2(72.436,143.549)
  other v1: 71.517,59.766 72.436,143.549
B_LN1_1_N: D6_3.4 D6_3.7 J3_3.5 U10_1.26 | length 26
  TOP_L1 w0.109: v1(41.907,148.587) 41.909,148.585 41.909,148.306 42.415,147.8 42.8,147.8 43.222,148.222 43.222,151.506 43.124,151.604 D6_3.7@43.124,152.717 43.124,152.954 43.222,153.052 43.222,153.816 43.22,153.818 43.22,154.38 J3_3.5@43.124,154.475 ; v1@44.401,147.6 44.598,147.402 46.296,147.402 47.167,146.531 47.502,146.531 47.556,146.531 ccw(c47.556,146.713) 47.738,146.713 47.738,146.733 cw(c47.92,146.733) 48.101,146.733 48.101,146.713 ccw(c48.283,146.713) 48.283,146.531 49.01,146.531 49.121,146.42 50.485,145.056 50.485,142.063 50.582,141.966 U10_1.26@50.582,141.791
  L3 w0.104: v1(41.907,148.587) 41.9,148.58 41.9,148.314 42.131,148.084 42.284,148.084 42.537,148.337 42.537,149.67 42.812,149.944 43.585,149.944 43.93,149.599 43.93,147.494 44.022,147.402 44.202,147.402 v1(44.4,147.6)
  other v2: 44.4,147.6 41.907,148.587
B_LN1_1_P: D6_3.5 D6_3.6 J3_3.6 U10_1.27 | length 26.1
  TOP_L1 w0.109: v1(41.412,148.092) 41.414,148.09 41.693,148.09 42.289,147.495 42.926,147.495 43.527,148.096 43.527,151.506 43.624,151.604 D6_3.5@43.624,151.842 D6_3.6@43.624,152.717 43.624,152.954 43.527,153.052 43.527,153.816 43.529,153.818 43.529,154.38 J3_3.6@43.624,154.475 ; v1@44.401,146.9 44.598,147.098 46.17,147.098 47.041,146.226 48.883,146.226 50.18,144.93 50.18,142.063 50.082,141.966 U10_1.27@50.082,141.791
  L3 w0.104: v1(41.412,148.092) 41.419,148.099 41.685,148.099 42.005,147.779 42.41,147.779 42.842,148.211 42.842,149.543 42.938,149.64 43.458,149.64 43.626,149.472 43.626,147.368 43.896,147.098 44.202,147.098 v1(44.4,146.9)
  other v2: 44.4,146.9 41.412,148.092
B_LN1_2_N: D6_2.4 D6_2.7 J3_2.5 U10_2.26 | length 22.3
  TOP_L1 w0.109: U10_2.26@62.182,141.791 62.112,141.861 62.112,142.105 62.085,142.132 62.085,148.053 62.426,148.395 63.038,148.395 63.166,148.267 63.166,148.086 v2(62.968,147.888) ; v2(63.551,149.628) 63.828,149.628 64.095,149.895 70.895,149.895 71.222,150.222 71.222,151.506 71.124,151.604 D6_2.4@71.124,151.842 D6_2.7@71.124,152.717 71.124,152.954 71.222,153.052 71.222,153.816 71.22,153.818 71.22,154.38 J3_2.5@71.124,154.475
  L3 w0.104: v2(62.968,147.888) 63.166,148.086 63.166,148.304 63.16,148.31 63.16,148.947 63.551,149.338 v2(63.551,149.628)
  other v1: 62.968,147.888 63.551,149.628
B_LN1_2_P: D6_2.5 D6_2.6 J3_2.6 U10_2.27 | length 23.3
  TOP_L1 w0.109: U10_2.27@61.682,141.791 61.753,141.861 61.753,142.105 61.78,142.132 61.78,148.18 62.3,148.7 63.164,148.7 63.47,148.393 63.47,148.086 v1(63.668,147.888) ; v2(64.046,149.133) 64.046,149.415 64.221,149.59 71.021,149.59 71.527,150.096 71.527,151.506 71.624,151.604 D6_2.5@71.624,151.842 D6_2.6@71.624,152.717 71.624,152.954 71.527,153.052 71.527,153.816 71.529,153.818 71.529,154.38 J3_2.6@71.624,154.475
  L3 w0.104: v1(63.668,147.888) 63.47,148.086 63.47,148.431 63.465,148.436 63.465,148.821 63.777,149.133 v2(64.046,149.133)
  other v1: 64.046,149.133
  other v2: 63.668,147.888
B_LN1_3_N: U10_3.26 U22.F4 | length 113.6
  TOP_L1 w0.064: 72.877,58.75 73.825,58.75
  TOP_L1 w0.084: 72.827,58.8 72.877,58.75 ; 73.825,58.75 73.925,58.85 U22.F4@74.075,59
  TOP_L1 w0.086: v2(71.517,58.8) 71.548,58.831 71.633,58.831 71.65,58.848 72.78,58.848 72.827,58.8
  TOP_L1 w0.109: U10_3.26@73.7,142.083 73.692,142.091 73.692,142.437 73.989,142.734 73.989,143.015 74.01,143.035 74.01,143.122 v2(74.036,143.149)
  L3 w0.104: v2(71.517,58.8) 71.545,58.828 71.631,58.828 71.651,58.848 71.988,58.848 72.407,59.267 72.407,63.852 74.389,65.834 74.389,79.343 85.675,90.629 85.675,106.143 84.189,107.629 84.189,119.237 90.112,125.161 90.112,134.757 86.609,138.26 86.587,138.26 85.106,138.26 85.078,138.26 84.902,138.436 84.902,139.667 84.628,139.941 83.876,139.941 83.597,139.662 83.597,138.331 83.502,138.236 82.92,138.236 82.702,138.454 82.702,139.783 82.249,140.236 81.732,140.236 81.204,139.708 80.33,139.708 79.791,140.247 75.638,140.247 73.989,141.897 73.989,143.015 74.009,143.035 74.009,143.121 v2(74.036,143.149)
  other v1: 71.517,58.8 74.036,143.149
B_LN1_3_P: U10_3.27 U22.G4 | length 113.8
  TOP_L1 w0.084: 73.126,59 U22.G4@73.575,59
  TOP_L1 w0.086: v1(71.517,59.2) 71.548,59.169 71.633,59.169 71.65,59.153 72.973,59.153 73.126,59
  TOP_L1 w0.109: U10_3.27@73.282,141.791 73.353,141.861 73.353,142.071 73.388,142.106 73.388,142.564 73.684,142.86 73.684,143.015 73.663,143.035 73.663,143.122 v2(73.636,143.149)
  L3 w0.104: v1(71.517,59.2) 71.545,59.172 71.631,59.172 71.651,59.153 71.861,59.153 72.102,59.394 72.102,63.978 74.084,65.96 74.084,79.469 85.371,90.755 85.371,106.016 83.884,107.503 83.884,119.364 89.808,125.287 89.808,134.631 86.483,137.955 84.952,137.955 84.597,138.31 84.597,139.541 84.502,139.636 84.002,139.636 83.902,139.536 83.902,138.205 83.628,137.931 82.793,137.931 82.397,138.327 82.397,139.657 82.123,139.931 81.858,139.931 81.509,139.582 81.457,139.53 ccw(c81.674,139.314) 81.454,139.527 ccw(c81.673,139.314) 81.368,139.314 81.368,138.955 cw(c81.189,138.955) 81.01,138.955 81.01,139.224 ccw(c80.831,139.224) 80.831,139.403 80.317,139.403 80.204,139.403 79.665,139.942 75.512,139.942 73.684,141.77 73.684,143.015 73.664,143.035 73.664,143.121 v2(73.636,143.149)
  other v1: 73.636,143.149
  other v2: 71.517,59.2
B_LN2_1_N: D7_3.4 D7_3.7 J3_3.11 U10_1.24 | length 26
  TOP_L1 w0.109: J3_3.11@46.124,154.475 46.22,154.38 46.22,153.818 46.222,153.816 46.222,153.052 46.124,152.954 D7_3.7@46.124,152.717 46.124,151.604 46.222,151.506 46.222,150.527 46.427,150.322 46.427,149.666 46.3,149.538 v2(46.3,149.5) ; v1(51.095,146.795) 51.096,146.515 51.485,146.126 51.485,142.063 51.582,141.966 U10_1.24@51.582,141.791
  L3 w0.104: v2(46.3,149.5) 46.3,149.527 46.498,149.724 46.498,150.227 46.366,150.358 45.645,150.358 45.455,150.169 45.455,149.854 45.455,149.139 ccw(c45.634,149.139) 45.633,148.959 45.64,148.959 cw(c45.638,148.78) 45.817,148.779 cw(c45.638,148.78) 45.637,148.601 ccw(c45.635,148.422) 45.456,148.424 ccw(c45.635,148.422) 45.634,148.243 45.733,148.242 cw(c45.731,148.063) 45.911,148.062 cw(c45.731,148.063) 45.73,147.884 45.635,147.885 ccw(c45.634,147.706) 45.455,147.706 45.455,147.463 45.479,147.439 45.532,147.386 45.639,147.279 47.365,147.279 48.186,147.279 48.582,146.884 48.582,145.177 48.798,144.96 49.231,144.96 49.448,145.177 49.448,146.884 49.843,147.279 50.11,147.279 50.331,147.279 50.816,146.795 v1(51.095,146.795)
  other v1: 46.3,149.5
  other v2: 51.095,146.795
B_LN2_1_P: D7_3.5 D7_3.6 J3_3.12 U10_1.25 | length 26
  TOP_L1 w0.109: J3_3.12@46.624,154.475 46.529,154.38 46.529,153.818 46.527,153.816 46.527,153.052 46.624,152.954 D7_3.6@46.624,152.717 D7_3.5@46.624,151.842 46.624,151.604 46.527,151.506 46.527,150.654 46.732,150.448 46.732,149.768 v2(47,149.5) ; v1(50.6,146.3) 50.88,146.299 51.18,146 51.18,142.063 51.082,141.966 U10_1.25@51.082,141.791
  L3 w0.104: v2(47,149.5) 47,149.527 46.802,149.724 46.802,150.353 46.624,150.532 46.493,150.663 45.518,150.663 45.329,150.473 45.15,150.295 45.15,147.337 45.512,146.974 47.365,146.974 48.06,146.974 48.277,146.758 48.277,145.05 48.672,144.655 49.357,144.655 49.753,145.05 49.753,146.758 49.969,146.974 50.11,146.974 50.205,146.974 50.6,146.579 v1(50.6,146.3)
  other v1: 47,149.5
  other v2: 50.6,146.3
B_LN2_2_N: D7_2.4 D7_2.7 J3_2.11 U10_2.24 | length 22.6
  TOP_L1 w0.109: U10_2.24@63.182,141.791 63.182,141.966 63.085,142.064 63.085,145.665 63.364,145.945 63.975,145.945 64.103,145.817 64.103,145.636 v1(63.906,145.437) ; v2(64.489,147.177) 64.766,147.177 66.193,148.605 72.127,148.605 74.222,150.7 74.222,151.506 74.124,151.604 D7_2.4@74.124,151.842 D7_2.7@74.124,152.717 74.124,152.954 74.222,153.052 74.222,153.816 74.22,153.818 74.22,154.38 J3_2.11@74.124,154.475
  L3 w0.104: v1(63.906,145.437) 64.103,145.635 64.103,145.854 64.098,145.86 64.098,146.497 64.489,146.888 v2(64.489,147.177)
  other v1: 64.489,147.177
  other v2: 63.906,145.437
B_LN2_2_P: D7_2.5 D7_2.6 J3_2.12 U10_2.25 | length 23.6
  TOP_L1 w0.109: U10_2.25@62.682,141.791 62.682,141.966 62.78,142.064 62.78,145.792 63.238,146.249 64.102,146.249 64.408,145.943 64.408,145.636 v2(64.606,145.437) ; v2(64.984,146.682) 64.984,146.964 66.32,148.3 72.253,148.3 74.527,150.573 74.527,151.506 74.624,151.604 D7_2.5@74.624,151.842 D7_2.6@74.624,152.717 74.624,152.954 74.527,153.052 74.527,153.816 74.529,153.818 74.529,154.38 J3_2.12@74.624,154.475
  L3 w0.104: v2(64.606,145.437) 64.408,145.635 64.408,145.98 64.402,145.986 64.402,146.37 64.714,146.682 v2(64.984,146.682)
  other v1: 64.606,145.437 64.984,146.682
B_LN2_3_N: U10_3.24 U22.F5 | length 113.8
  TOP_L1 w0.064: 73.076,58.196 73.422,58.196 73.423,58.198 73.425,58.198 73.473,58.246 73.68,58.246 73.905,58.47
  TOP_L1 w0.084: 73.075,58.195 73.076,58.196 ; 73.905,58.47 74.045,58.47 U22.F5@74.075,58.5
  TOP_L1 w0.086: v1(71.517,57.834) 71.548,57.866 71.633,57.866 71.65,57.882 72.35,57.882 72.663,58.195 73.075,58.195
  TOP_L1 w0.109: U10_3.24@74.782,141.791 74.782,141.966 74.685,142.064 74.685,142.319 74.821,142.456 74.911,142.456 75.189,142.734 75.189,143.015 75.21,143.035 75.21,143.122 v1(75.236,143.149)
  L3 w0.104: v1(71.517,57.834) 71.545,57.862 71.631,57.862 71.651,57.882 72.4,57.882 73.163,58.645 73.163,61 73.163,63.19 75.31,65.337 75.489,65.516 75.489,79.028 86.675,90.215 86.675,106.602 85.168,108.109 85.168,118.832 91.091,124.755 91.091,136.109 88.131,139.069 87.026,139.069 86.883,139.212 86.883,139.495 87.403,140.016 87.403,140.566 86.972,140.997 76.018,140.997 75.189,141.826 75.189,143.015 75.209,143.035 75.209,143.121 v1(75.236,143.149)
  other v2: 71.517,57.834 75.236,143.149
B_LN2_3_P: U10_3.25 U22.G5 | length 113.7
  TOP_L1 w0.084: 73.075,58.5 73.076,58.499 73.297,58.499 73.298,58.5 U22.G5@73.575,58.5
  TOP_L1 w0.086: v1(71.517,58.234) 71.548,58.203 71.633,58.203 71.65,58.187 72.224,58.187 72.537,58.5 73.075,58.5
  TOP_L1 w0.109: U10_3.25@74.282,141.791 74.282,141.966 74.38,142.064 74.38,142.445 74.695,142.76 74.784,142.76 74.884,142.86 74.884,143.015 74.863,143.035 74.863,143.122 v2(74.836,143.149)
  L3 w0.104: v1(71.517,58.234) 71.545,58.207 71.631,58.207 71.651,58.187 72.274,58.187 72.859,58.772 72.859,63.317 75.184,65.642 75.184,79.155 86.371,90.341 86.371,106.475 84.863,107.983 84.863,118.958 90.787,124.882 90.787,135.983 90.407,136.363 90.37,136.4 ccw(c90.243,136.273) 90.117,136.4 90.027,136.31 cw(c89.9,136.437) 89.774,136.31 cw(c89.9,136.437) 89.774,136.563 89.863,136.653 ccw(c89.737,136.779) 89.863,136.906 ccw(c89.737,136.779) 89.61,136.906 cw(c89.484,137.033) 89.357,136.906 cw(c89.484,137.033) 89.357,137.159 ccw(c89.23,137.286) 89.357,137.413 88.523,138.246 88.486,138.283 88.005,138.765 86.9,138.765 86.578,139.086 86.578,139.622 87.099,140.142 87.099,140.439 86.846,140.692 75.892,140.692 74.884,141.7 74.884,143.015 74.864,143.035 74.864,143.121 v2(74.836,143.149)
  other v1: 74.836,143.149
  other v2: 71.517,58.234
B_LN3_1_N: D8_3.1 D8_3.10 J3_3.14 U10_1.22 | length 26
  TOP_L1 w0.109: J3_3.14@47.624,154.475 47.72,154.38 47.72,153.818 47.722,153.816 47.722,153.052 47.624,152.954 47.624,151.604 47.722,151.506 47.722,150.547 48.269,150 49.111,150 49.311,149.8 49.311,149.195 49.172,149.056 48.793,149.056 v1(48.594,149.254) ; U10_1.22@52.582,141.791 52.512,141.861 52.512,142.137 52.485,142.164 52.485,146.402 v1@52.682,146.599
  L3 w0.104: v1(48.594,149.254) 48.792,149.056 55.977,149.056 56.355,148.678 56.355,147.788 56.062,147.495 52.738,147.495 52.485,147.241 52.485,146.798 v1(52.682,146.6)
  other v2: 52.682,146.6 48.594,149.254
B_LN3_1_P: D8_3.2 D8_3.9 J3_3.15 U10_1.23 | length 26
  TOP_L1 w0.109: J3_3.15@48.124,154.475 48.029,154.38 48.029,153.818 48.027,153.816 48.027,153.052 48.124,152.954 48.124,151.604 48.027,151.506 48.027,150.673 48.395,150.305 49.237,150.305 49.616,149.926 49.616,149.068 49.298,148.751 48.793,148.751 v2(48.594,148.554) ; v1@51.982,146.599 52.18,146.402 52.18,142.164 52.153,142.137 52.153,141.861 U10_1.23@52.082,141.791
  L3 w0.104: v2(48.594,148.554) 48.792,148.751 55.85,148.751 56.05,148.551 56.05,147.914 55.936,147.8 52.612,147.8 52.18,147.367 52.18,146.798 v1(51.982,146.6)
  other v1: 48.594,148.554
  other v2: 51.982,146.6
B_LN3_2_N: D8_2.1 D8_2.10 J3_2.14 U10_2.22 | length 22.6
  TOP_L1 w0.109: U10_2.22@64.182,141.791 64.112,141.861 64.112,142.137 64.085,142.164 64.085,143.475 64.212,143.603 64.705,143.603 64.843,143.465 v2(64.844,143.185) ; v1(75.524,150.8) 75.722,150.998 75.722,151.506 75.624,151.604 75.624,152.954 75.722,153.052 75.722,153.661 75.722,153.768 75.72,153.77 75.72,154.38 J3_2.14@75.624,154.475
  L3 w0.104: v2(64.844,143.185) 64.844,143.517 64.66,143.7 64.66,144.15 66.911,146.4 68.569,146.4 69.369,147.2 73.274,147.2 73.7,147.2 75.722,149.222 75.722,149.259 75.722,150.602 v1(75.524,150.8)
  other v1: 64.843,143.185
  other v2: 75.524,150.8
B_LN3_2_P: D8_2.2 D8_2.9 J3_2.15 U10_2.23 | length 22.9
  TOP_L1 w0.109: U10_2.23@63.682,141.966 63.753,142.036 63.753,142.137 63.78,142.164 63.78,143.601 64.086,143.908 64.831,143.908 65.059,143.68 v1(65.338,143.68) ; 76.027,153.535 76.027,153.816 76.029,153.818 76.029,154.38 J3_2.15@76.124,154.475 ; 76.027,153.559 76.027,153.052 76.124,152.954 76.124,151.604 76.027,151.506 76.027,150.998 v1(76.224,150.8)
  L3 w0.104: v1(65.338,143.68) 65.314,143.704 65.087,143.704 64.965,143.826 64.965,144.023 67.037,146.095 68.695,146.095 68.874,146.274 69.495,146.895 73.579,146.895 73.826,146.895 75.956,149.025 76.027,149.096 76.027,150.602 v1(76.224,150.8)
  other v2: 65.339,143.68 76.224,150.8
B_LN3_3_N: U10_3.22 U22.F6 | length 113.8
  TOP_L1 w0.064: 73.438,57.746 73.821,57.746 U22.F6@74.075,58
  TOP_L1 w0.084: 73.291,57.598 73.438,57.746
  TOP_L1 w0.086: v1(71.517,56.869) 71.573,56.924 72.617,56.924 73.291,57.598
  TOP_L1 w0.109: U10_3.22@75.782,141.791 75.782,141.966 75.685,142.064 75.685,142.319 75.748,142.383 75.911,142.383 76.085,142.556 76.175,142.556 v1(76.202,142.583)
  L3 w0.104: v1(71.517,56.869) 71.545,56.897 71.631,56.897 71.651,56.916 72.758,56.916 73.075,57.233 73.291,57.449 74.032,58.19 74.032,61 74.032,62.757 76.499,65.224 76.499,78.61 87.665,89.776 87.665,107.012 86.089,108.588 86.089,118.479 91.992,124.382 91.992,137.496 91.813,137.674 87.929,141.558 87.751,141.737 76.508,141.737 75.941,142.303 75.941,142.39 76.074,142.522 76.102,142.522 76.163,142.583 v1(76.202,142.583)
  other v2: 71.517,56.869 76.202,142.583
B_LN3_3_P: U10_3.23 U22.G6 | length 113.8
  TOP_L1 w0.064: 73.298,58 U22.G6@73.575,58
  TOP_L1 w0.084: 73.077,57.812 73.263,57.997 73.296,57.997 73.297,57.999 73.298,58
  TOP_L1 w0.086: v1(71.517,57.269) 71.557,57.229 72.491,57.229 73.073,57.812 73.077,57.812
  TOP_L1 w0.109: U10_3.23@75.282,141.791 75.282,141.966 75.38,142.064 75.38,142.445 75.622,142.688 75.785,142.688 75.849,142.752 75.849,142.758 75.919,142.828 v1(75.919,142.866)
  L3 w0.104: v1(71.517,57.269) 71.545,57.241 71.631,57.241 71.651,57.221 72.632,57.221 73.727,58.316 73.727,62.884 76.194,65.351 76.194,78.736 87.36,89.902 87.36,106.885 85.784,108.462 85.784,118.605 91.687,124.509 91.687,137.37 90.941,138.116 90.904,138.152 ccw(c90.778,138.026) 90.651,138.153 90.584,138.085 cw(c90.457,138.212) 90.33,138.085 cw(c90.457,138.212) 90.33,138.338 90.398,138.406 ccw(c90.271,138.532) 90.398,138.659 89.693,139.364 89.656,139.401 87.625,141.432 76.382,141.432 75.636,142.177 75.636,142.516 75.858,142.738 75.858,142.766 75.919,142.827 v1(75.919,142.866)
  other v2: 71.517,57.269 75.919,142.866
BOOT0: JANALOG.1 R151.1 R352.2 R385.1 TP90.X | length 151.4
  TOP_L1 w0.127: v3(39.814,20.466) 39.556,20.724 39.446,20.724 38.868,21.302 38.868,21.59 39.341,22.063 40.102,22.063 41.54,23.502 50.036,23.502 50.612,24.078 50.612,30.262 51.203,30.853 51.203,37.938 54.264,40.999 60.096,40.999 66.407,47.31 66.407,55.28 66.735,55.607 66.735,61.465 55.523,72.677 55.523,75.608 54.166,76.964 49.68,76.964 49.384,76.668 49.384,75.932 49.504,75.813 49.504,72.412 49.263,72.171 49.263,70.38 49.486,70.157 51.238,70.157 51.421,70.34 R352.2@51.77,70.34 ; R352.2@51.789,70.34 R352.2@51.77,70.34 ; R151.1@51.789,70.89 51.789,70.32 R352.2@51.77,70.34
  L8 w0.127: JANALOG.1@27.94,2.54 28.929,3.529 32.077,3.529 v4(32.094,3.545)
  BOTTOM_L10 w0.127: TP90.X@22.86,5.08 23.647,5.867 26.514,5.867 26.73,5.651 26.73,3.75 JANALOG.1@27.94,2.54 ; v4(32.094,3.545) 32.094,4.021 32.063,4.051 32.063,5.038 31.32,5.781 29.703,5.781 29.456,6.028 29.456,9.469 31.478,11.492 36.315,11.492 37.56,12.737 37.56,13.426 39.814,15.68 39.814,20.499 39.702,20.612 39.702,21.32 40.904,22.523 47.611,22.523 48.728,21.406 48.728,16.956 R385.1@48.936,16.749
  other v1: 39.814,20.466
  other v2: 39.814,20.466
  other v3: 32.094,3.545
  other v4: 39.814,20.466
  other v5: 39.814,20.466
CLKBUF_PD_25: R209.2 R295.1 U34.AP28 | length 3.9
  TOP_L1 w0.079: 39.056,37.961 39.049,37.954 39.079,37.924 39.079,37.804 39.081,37.802 39.081,37.726 39.091,37.715 39.091,37.712
  TOP_L1 w0.1: R295.1@37.486,39.824 R209.2@37.486,39.224 37.501,39.224 37.811,38.914 37.811,38.509 38.119,38.202 38.326,38.202 38.439,38.089 38.928,38.089 39.056,37.961 ; U34.AP28@39.091,37.019 39.091,37.332 39.091,37.712
CLKREQ_N_1V8: MODULE1.AW17 R320.2 U21_4.3 | length 44
  TOP_L1 w0.084: U21_4.3@47.05,73.841 v1@47.05,74.566 ; v2(47.1,74.641) R320.2@47.1,75.016
  TOP_L1 w0.127: v2(62.082,101.236) 66.882,101.236 MODULE1.AW17@67.482,100.636
  L3 w0.127: v2(47.1,74.641) 47.43,74.971 47.959,74.971 47.998,75.011 50.318,75.011 50.357,74.971 51.492,74.971 51.641,75.12 51.641,76.515 50.768,77.388 50.768,91.683 58.621,99.536 60.914,99.536 62.082,100.704 v2(62.082,101.236)
  other v1: 47.1,74.641 62.082,101.236
CLKREQ_N_3V3_24: R328.2 U21_4.9 U34.AM34 | length 73.1
  TOP_L1 w0.084: U21_4.9@47.05,72.441 47.05,71.568 47.2,71.418 v1(47.2,71.412)
  TOP_L1 w0.1: 36.615,36.849 36.958,36.849 37.121,36.849 37.421,36.549 U34.AM34@37.421,36.349
  TOP_L1 w0.127: 36.615,36.849 36.342,37.122 36.342,37.795 36.958,38.411 36.958,42.478 40.218,45.738 40.218,50.599 41.686,52.067 58.117,52.067 59.476,53.425 59.476,54.665 60.028,55.217 64.028,55.217 65.146,56.335 65.146,60.807 62.745,63.208 60.518,63.208 59.826,63.9 59.826,64.813 57.16,67.48 52.7,67.48 v2(51.84,68.34)
  L3 w0.127: v1(47.2,71.412) 48.225,70.388 49.808,70.388 51.84,68.355 v2(51.84,68.34)
  other v1: 51.84,68.34
  other v2: 47.2,71.412
CSI0_CK_N: MODULE1.AK45 U10_2.15 | length 15
  TOP_L1 w0.109: MODULE1.AK45@56.682,134.236 56.83,134.68 v1(56.882,134.836) ; v1(63.139,137.696) 63.112,137.723 63.112,137.803 63.085,137.83 63.085,138.218 63.182,138.316 U10_2.15@63.182,138.491
  L3 w0.104: v1(56.882,134.836) 56.85,134.868 56.85,134.952 56.834,134.968 56.834,137.141 58.514,138.821 58.728,138.821 59.138,138.821 cw(c59.138,138.642) 59.317,138.642 59.317,138.493 ccw(c59.496,138.493) 59.496,138.314 ccw(c59.496,138.493) 59.675,138.493 59.675,138.642 cw(c59.854,138.642) 59.854,138.821 cw(c59.854,138.642) 60.033,138.642 60.033,138.493 ccw(c60.212,138.493) 60.212,138.314 ccw(c60.212,138.493) 60.391,138.493 60.391,138.642 cw(c60.57,138.642) 60.57,138.821 cw(c60.57,138.642) 60.749,138.642 60.749,138.544 ccw(c60.928,138.544) 60.928,138.365 ccw(c60.928,138.544) 61.107,138.544 61.107,138.642 cw(c61.286,138.642) 61.286,138.821 62.886,138.821 63.131,138.821 63.771,138.181 63.771,137.733 63.564,137.525 63.254,137.525 63.205,137.574 63.205,137.585 63.139,137.651 v1(63.139,137.696)
  other v2: 56.882,134.836 63.139,137.696
CSI0_CK_P: MODULE1.AK46 U10_2.14 | length 15
  TOP_L1 w0.109: v1(56.482,134.836) 56.534,134.992 MODULE1.AK46@56.682,135.436 ; U10_2.14@62.682,138.491 62.682,138.316 62.78,138.218 62.78,137.624 62.829,137.575 62.829,137.44 v1(62.856,137.413)
  L3 w0.104: v1(56.482,134.836) 56.514,134.868 56.514,134.952 56.53,134.968 56.53,137.268 58.388,139.126 63.258,139.126 64.076,138.307 64.076,137.607 63.69,137.221 63.127,137.221 62.995,137.353 62.961,137.353 62.901,137.413 v1(62.856,137.413)
  other v2: 56.482,134.836 62.856,137.413
CSI0_L0_N: MODULE1.AL44 U10_2.6 | length 14.9
  TOP_L1 w0.109: v2(57.482,132.436) 57.482,132.48 57.549,132.547 57.549,132.557 57.592,132.6 57.592,132.698 57.882,132.988 MODULE1.AL44@57.882,133.036 ; v1(58.082,136.036) 58.055,136.063 58.055,136.15 58.034,136.17 58.034,136.399 57.792,136.642 56.817,136.642 56.511,136.336 55.635,136.336 55.539,136.432 55.539,136.801 55.957,137.219 58.091,137.219 58.429,136.881 58.565,136.881 58.661,136.977 58.661,137.149 58.273,137.537 58.273,137.673 58.566,137.965 58.566,138.199 58.682,138.316 U10_2.6@58.682,138.491
  L3 w0.104: v2(57.482,132.436) 57.482,132.476 57.403,132.554 57.403,132.811 56.705,133.51 56.705,133.819 56.797,133.91 57.764,133.91 58.034,134.18 58.06,134.206 58.071,134.217 58.071,134.917 57.893,135.096 57.757,135.231 57.757,135.361 58.027,135.631 58.027,135.877 58.054,135.905 58.054,136.008 v1(58.082,136.036)
  other v1: 57.482,132.436
  other v2: 58.082,136.036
